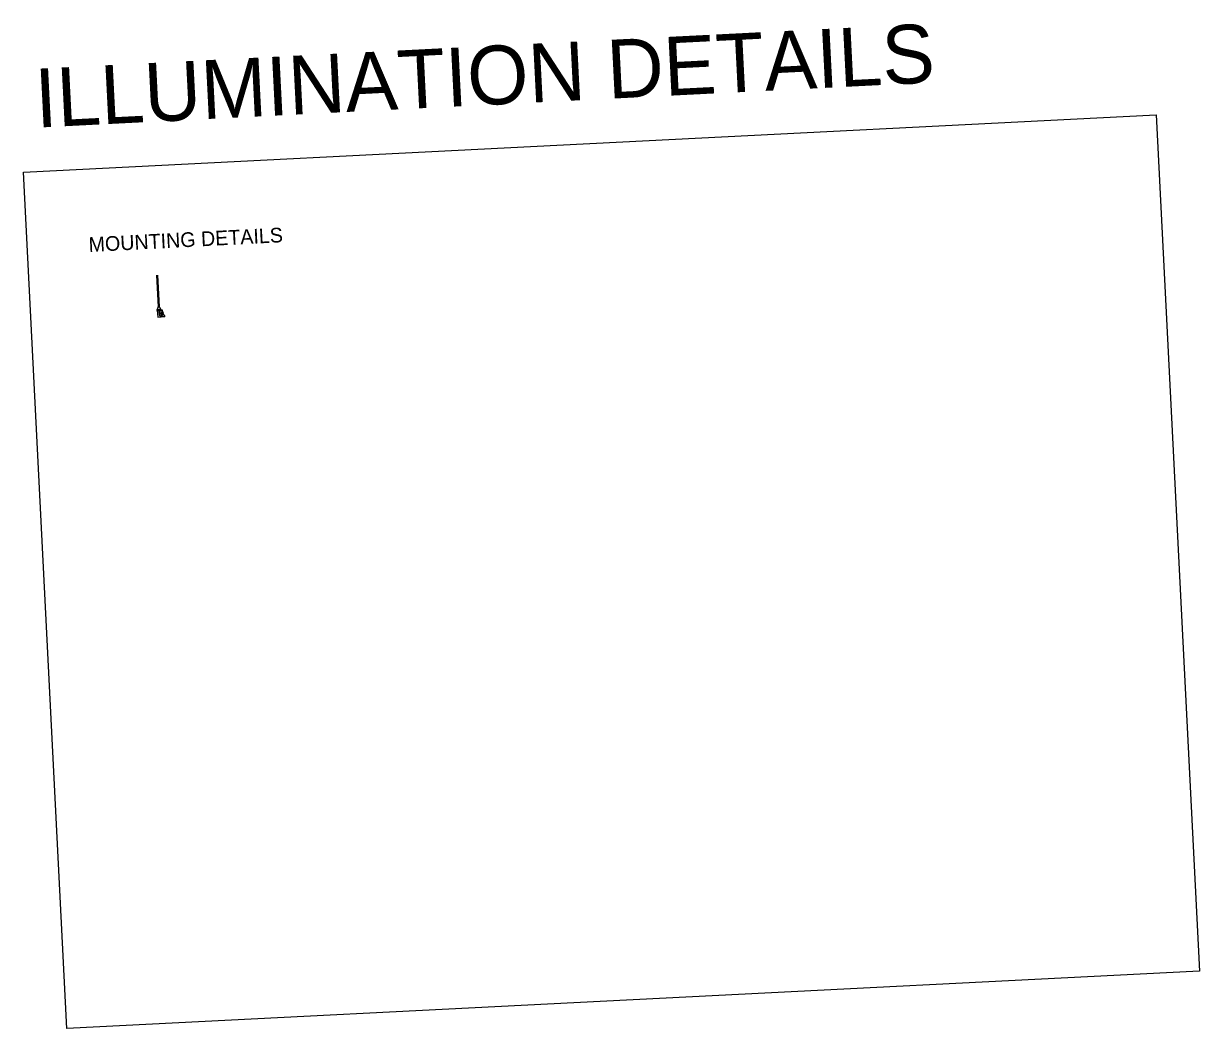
# Model space of a CAD drawing. Extents: x 1710192 to 1712821, y 543277 to 545689.
# Drawn here: x 1710192.3 to 1710672.1, y 543594.9 to 544005.1 of the extents above; entities that cross this region are included whole.
import ezdxf

# ---------------------------------------------------------------- set-up
doc = ezdxf.new("R2010")
doc.units = 0
for name, color, linetype in [('GreenPencil', 7, 'Continuous'), ('Railing', 7, 'Continuous'), ('t_Conduit CL', 7, 'Continuous'), ('t_Conduit Inside', 7, 'Continuous'), ('t_Conduit Outside', 7, 'Continuous'), ('t_Light Pole', 7, 'Continuous'), ('t_Light Pole Base', 7, 'Continuous'), ('t_Light Pole Bracket', 7, 'Continuous'), ('t_Polymer Junction Box', 7, 'Continuous')]:
    doc.layers.add(name, color=color, linetype=linetype)

msp = doc.modelspace()

# ---------------------------------------------------------------- linework, layer by layer
at = {"layer": 'GreenPencil'}
msp.add_lwpolyline([(1710192.33, 543944.48), (1710654.44, 543967.8), (1710672.08, 543618.28), (1710209.97, 543594.95)], close=True, dxfattribs=at)
at = {"layer": 'Railing'}
for p, q in [((1710248.39, 543888.13), (1710248.33, 543888.07)), ((1710248.33, 543888.07), (1710248.35, 543887.73)), ((1710248.35, 543887.73), (1710248.42, 543887.7)), ((1710248.42, 543887.7), (1710248.36, 543887.65)), ((1710248.36, 543887.65), (1710248.38, 543887.21)), ((1710248.38, 543887.21), (1710248.44, 543887.17)), ((1710248.44, 543887.17), (1710248.38, 543887.12)), ((1710248.38, 543887.12), (1710248.4, 543886.86)), ((1710249.02, 543888.16), (1710248.39, 543888.13)), ((1710248.4, 543886.86), (1710248.46, 543886.82)), ((1710248.46, 543886.82), (1710248.4, 543886.78)), ((1710248.4, 543886.78), (1710248.41, 543886.5)), ((1710248.41, 543886.5), (1710248.48, 543886.47)), ((1710248.48, 543886.47), (1710248.42, 543886.42)), ((1710248.42, 543886.42), (1710248.46, 543885.66)), ((1710249.09, 543888.11), (1710249.02, 543888.16)), ((1710249.33, 543886.59), (1710249.09, 543888.11)), ((1710249.95, 543885.79), (1710249.33, 543886.59)), ((1710249.97, 543885.46), (1710249.95, 543885.79)), ((1710248.46, 543885.66), (1710248.52, 543885.63)), ((1710248.52, 543885.63), (1710248.46, 543885.58)), ((1710248.46, 543885.58), (1710248.47, 543885.38)), ((1710249.97, 543885.46), (1710248.47, 543885.38))]:
    msp.add_line(p, q, dxfattribs=at)
at = {"layer": 't_Conduit CL'}
for p, q in [((1710247.63, 543888.03), (1710247.6, 543888.53)), ((1710247.63, 543888.03), (1710247.72, 543886.27)), ((1710248.97, 543886.79), (1710249.03, 543886.41))]:
    msp.add_line(p, q, dxfattribs=at)
msp.add_arc((1710248.38, 543886.3), 0.661, 182.8897, 8.8987, dxfattribs=at)
at = {"layer": 't_Conduit Inside'}
for p, q in [((1710247.6, 543888.03), (1710247.57, 543888.53)), ((1710247.6, 543888.03), (1710247.69, 543886.27)), ((1710247.66, 543888.03), (1710247.63, 543888.53)), ((1710247.66, 543888.03), (1710247.75, 543886.28)), ((1710248.94, 543886.79), (1710249, 543886.39)), ((1710249, 543886.8), (1710249.06, 543886.41))]:
    msp.add_line(p, q, dxfattribs=at)
for radius, start, end in [(0.692, 182.8897, 8.8987), (0.63, 182.322, 8.331)]:
    msp.add_arc((1710248.38, 543886.3), radius, start, end, dxfattribs=at)
at = {"layer": 't_Conduit Outside'}
for p, q in [((1710247.56, 543889.45), (1710246.9, 543902.43)), ((1710247.54, 543888.51), (1710247.54, 543888.53)), ((1710247.54, 543888.53), (1710247.66, 543888.53)), ((1710247.54, 543888.51), (1710247.67, 543888.51)), ((1710247.59, 543888.03), (1710247.56, 543888.53)), ((1710247.59, 543888.03), (1710247.67, 543886.27)), ((1710247.67, 543888.03), (1710247.64, 543888.53)), ((1710247.66, 543888.53), (1710247.67, 543888.51)), ((1710247.67, 543888.03), (1710247.76, 543886.27)), ((1710248.93, 543886.78), (1710248.99, 543886.4)), ((1710249.01, 543886.8), (1710249.07, 543886.41))]:
    msp.add_line(p, q, dxfattribs=at)
for radius in [0.703, 0.619]:
    msp.add_arc((1710248.38, 543886.3), radius, 182.8897, 8.8987, dxfattribs=at)
at = {"layer": 't_Light Pole'}
for p, q in [((1710247.35, 543889.44), (1710246.69, 543902.42)), ((1710247.37, 543889.44), (1710246.71, 543902.42)), ((1710247.74, 543889.46), (1710247.09, 543902.44)), ((1710247.76, 543889.46), (1710247.11, 543902.44))]:
    msp.add_line(p, q, dxfattribs=at)
at = {"layer": 't_Light Pole Base'}
for p, q in [((1710246.91, 543888.29), (1710247.3, 543889.31)), ((1710248.32, 543888.36), (1710246.91, 543888.29)), ((1710246.92, 543888), (1710246.91, 543888.29)), ((1710247.21, 543888.05), (1710246.92, 543888.04)), ((1710246.92, 543888), (1710247.21, 543888.01)), ((1710247.21, 543888.01), (1710247.21, 543888.05)), ((1710247.28, 543889.31), (1710247.27, 543889.37)), ((1710247.85, 543889.34), (1710247.28, 543889.31)), ((1710247.29, 543889.39), (1710247.31, 543889.39)), ((1710247.81, 543889.42), (1710247.31, 543889.39)), ((1710247.31, 543889.39), (1710247.31, 543889.41)), ((1710247.78, 543889.46), (1710247.33, 543889.43)), ((1710247.81, 543889.44), (1710247.81, 543889.42)), ((1710247.82, 543889.42), (1710247.81, 543889.42)), ((1710247.83, 543889.33), (1710248.32, 543888.36)), ((1710247.85, 543889.34), (1710247.84, 543889.4)), ((1710248.04, 543888.09), (1710248.33, 543888.11)), ((1710248.04, 543888.05), (1710248.04, 543888.09)), ((1710248.04, 543888.05), (1710248.33, 543888.07)), ((1710248.32, 543888.36), (1710248.33, 543888.07))]:
    msp.add_line(p, q, dxfattribs=at)
for centre, start, end in [((1710247.3, 543889.37), 92.8897, 182.8897), ((1710247.33, 543889.41), 92.8897, 182.8897), ((1710247.79, 543889.44), 2.8897, 92.8897), ((1710247.82, 543889.4), 2.8897, 92.8897)]:
    msp.add_arc(centre, 0.0208, start, end, dxfattribs=at)
at = {"layer": 't_Light Pole Bracket'}
for p, q in [((1710248.33, 543888.07), (1710246.92, 543888)), ((1710246.92, 543888), (1710247.06, 543885.31)), ((1710247.06, 543885.31), (1710248.47, 543885.38))]:
    msp.add_line(p, q, dxfattribs=at)
at = {"layer": 't_Polymer Junction Box'}
for p, q in [((1710249.1, 543887.39), (1710249.18, 543887.4)), ((1710249.2, 543886.76), (1710249.1, 543887.39)), ((1710249.18, 543887.4), (1710249.2, 543887.42)), ((1710249.28, 543886.77), (1710249.18, 543887.4)), ((1710249.2, 543886.76), (1710249.28, 543886.77)), ((1710249.28, 543886.77), (1710249.3, 543886.75))]:
    msp.add_line(p, q, dxfattribs=at)
msp.add_lwpolyline([(1710248.67, 543886.74), (1710248.59, 543887.24), (1710249.19, 543887.33), (1710249.27, 543886.84)], close=True, dxfattribs=at)
for radius in [0.104, 0.0833]:
    msp.add_circle((1710248.88, 543887.03), radius, dxfattribs=at)

# ---------------------------------------------------------------- texts
at = {"layer": 'GreenPencil'}
for s, height, p in [('ILLUMINATION DETAILS', 24, (1710197.6, 543962.6)), ('MOUNTING DETAILS', 6, (1710219.03, 543911.86))]:
    msp.add_text(s, height=height, rotation=2.8897, dxfattribs=at).set_placement(p)

doc.saveas('drawing.dxf')
